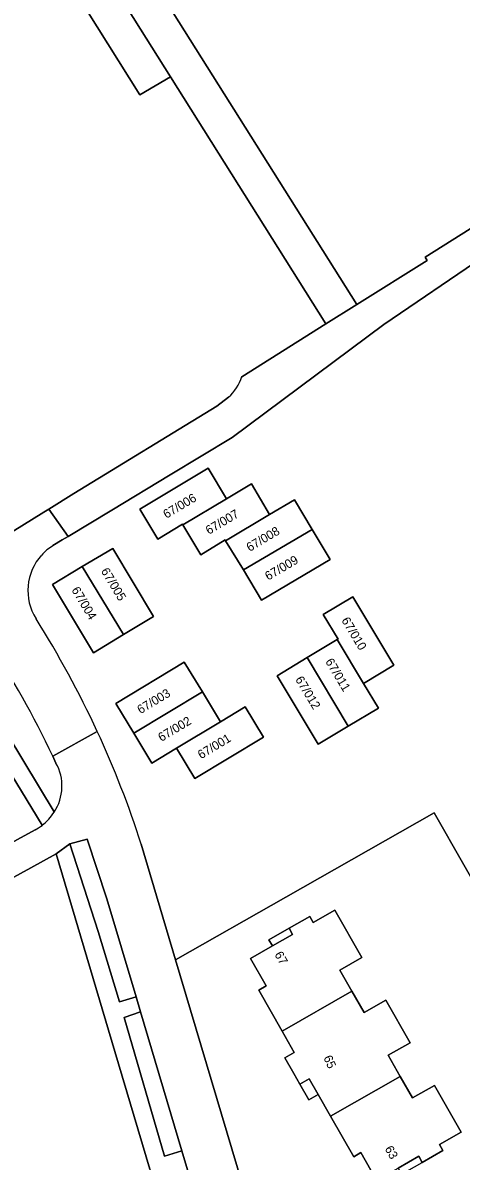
# Model space of a CAD drawing. Extents: x 158132 to 159664, y 385256 to 387218.
# Drawn here: x 158779.7 to 158829.4, y 386620.5 to 386749.8 of the extents above; entities that cross this region are included whole.
import ezdxf

# ---------------------------------------------------------------- set-up
doc = ezdxf.new("R2010")
doc.units = 0
for name, color, linetype in [('IMGEO_Berm_groen', 7, 'Continuous'), ('IMGEO_Erf', 7, 'Continuous'), ('IMGEO_Gemengd_bos', 7, 'Continuous'), ('IMGEO_Groenvoorziening', 7, 'Continuous'), ('IMGEO_Loofbos', 7, 'Continuous'), ('IMGEO_Pand', 7, 'Continuous'), ('IMGEO_Pand_nummerreeks', 7, 'Continuous'), ('IMGEO_Pand_overbouw', 7, 'Continuous'), ('IMGEO_Parkeervlak_open', 7, 'Continuous'), ('IMGEO_Rijbaan_lokaal_gesloten', 7, 'Continuous'), ('IMGEO_Voetpad_gesloten', 7, 'Continuous'), ('IMGEO_Voetpad_open', 7, 'Continuous')]:
    doc.layers.add(name, color=color, linetype=linetype)

msp = doc.modelspace()

# ---------------------------------------------------------------- linework, layer by layer
at = {"layer": 'IMGEO_Berm_groen'}
for points in [[(158775.73, 386679.59), (158772.63, 386677.75), (158783.24, 386660.19)], [(158783.43, 386665.75), (158783.08, 386666.53)]]:
    msp.add_lwpolyline(points, dxfattribs=at)
for centre, radius, start, end in [((158686.76, 386620.94), 106.56, 25.3313, 33.3917), ((158778.78, 386663.13), 5.34, 326.5723, 29.3728)]:
    msp.add_arc(centre, radius, start, end, dxfattribs=at)
at = {"layer": 'IMGEO_Erf'}
for points in [[(158839.81, 386636.46), (158826.35, 386660.11), (158809.51, 386650.52), (158797.01, 386643.41), (158808.08, 386606.17), (158832.23, 386594.34)], [(158819.82, 386618.36), (158818.03, 386621.5), (158817.22, 386621.04), (158814.6, 386625.63), (158813.19, 386628.12), (158812.12, 386627.51), (158811.11, 386629.29), (158810.43, 386630.5), (158809.42, 386632.26), (158810.48, 386632.86), (158809.09, 386635.3), (158806.44, 386639.95), (158807.3, 386640.44), (158805.52, 386643.57), (158808.01, 386644.99), (158807.61, 386645.69), (158809.89, 386646.98), (158812.24, 386648.33), (158812.63, 386647.65), (158815.07, 386649.04), (158818.14, 386643.66), (158815.65, 386642.24), (158817.03, 386639.83), (158818.4, 386637.41), (158820.87, 386638.82), (158823.62, 386633.99), (158821.13, 386632.57), (158822.51, 386630.14), (158823.89, 386627.71), (158826.39, 386629.13), (158829.42, 386623.81), (158826.96, 386622.41), (158827.35, 386621.74), (158824.99, 386620.4)]]:
    msp.add_lwpolyline(points, dxfattribs=at)
at = {"layer": 'IMGEO_Gemengd_bos'}
for points in [[(158804.53, 386709.63), (158814.08, 386715.63), (158796.45, 386743.69), (158792.95, 386741.63), (158783.28, 386757.12), (158786.68, 386759.23), (158770.04, 386785.73)], [(158831.89, 386723.22), (158820.63, 386715.54), (158803.45, 386702.74), (158796.4, 386698.49), (158789.76, 386694.48), (158784.81, 386691.49), (158784.15, 386691.09), (158783.09, 386690.44)], [(158778.46, 386692), (158782.07, 386694.24), (158782.63, 386694.59), (158785.45, 386696.37), (158801.69, 386706.29), (158803.02, 386707.3)], [(158793.12, 386656.52), (158797.01, 386643.41), (158809.51, 386650.52), (158826.35, 386660.11), (158839.81, 386636.46)]]:
    msp.add_lwpolyline(points, dxfattribs=at)
for points in [[(158812.52, 386692.26), (158814.55, 386688.86), (158806.76, 386684.26), (158804.7, 386687.68), (158802.69, 386691), (158802.63, 386691.1), (158799.86, 386689.41), (158797.84, 386692.81), (158797.8, 386692.87), (158794.99, 386691.18), (158792.95, 386694.59), (158800.72, 386699.23), (158802.79, 386695.77), (158805.61, 386697.45), (158807.68, 386693.98), (158810.49, 386695.66)], [(158794.52, 386682.4), (158791.1, 386680.33), (158787.69, 386678.27), (158783.03, 386686.04), (158786.42, 386688.07), (158789.88, 386690.13)], [(158821.79, 386676.87), (158818.34, 386674.8), (158820.02, 386672), (158816.61, 386669.95), (158813.21, 386667.91), (158808.54, 386675.67), (158811.95, 386677.72), (158815.36, 386679.77), (158815.46, 386679.83), (158813.74, 386682.63), (158817.12, 386684.63)], [(158806.97, 386668.7), (158799.21, 386664), (158797.13, 386667.43), (158794.33, 386665.74), (158792.28, 386669.13), (158790.23, 386672.52), (158797.99, 386677.22), (158800.05, 386673.83), (158802.1, 386670.44), (158804.9, 386672.14)]]:
    msp.add_lwpolyline(points, close=True, dxfattribs=at)
for centre, radius, start, end in [((158799.34, 386711.34), 5.47, 312.3991, 341.8129), ((158786.24, 386685.35), 5.98, 121.7641, 137.7233), ((158786.25, 386685.34), 6, 137.7119, 212.1777), ((158684.96, 386621.62), 113.66, 24.8208, 32.1691), ((158685.63, 386622.02), 112.89, 17.7969, 24.7835)]:
    msp.add_arc(centre, radius, start, end, dxfattribs=at)
at = {"layer": 'IMGEO_Groenvoorziening'}
for points in [[(158781.86, 386658.68), (158728.44, 386746.57)], [(158750.96, 386641.69), (158781.06, 386658.16)], [(158794.1, 386619.62), (158790.13, 386633), (158783.46, 386655.44), (158780.58, 386653.86), (158700.45, 386609.88), (158701.19, 386608.53), (158697.58, 386606.21)]]:
    msp.add_lwpolyline(points, dxfattribs=at)
for points in [[(158789.22, 386650.31), (158786.97, 386657.09), (158785.02, 386656.56), (158788.24, 386646.61), (158790.63, 386638.62), (158792.53, 386639.18)], [(158793.03, 386637.5), (158791.16, 386636.84), (158795.75, 386621.11), (158797.73, 386621.7)]]:
    msp.add_lwpolyline(points, close=True, dxfattribs=at)
msp.add_arc((158778.16, 386663.45), 6.04, 298.7274, 307.7499, dxfattribs=at)
at = {"layer": 'IMGEO_Loofbos'}
msp.add_lwpolyline([(158858.01, 386761.37), (158857.29, 386760.92), (158849.54, 386773.22), (158844.27, 386781.59), (158868.97, 386797.12), (158879.37, 386780.65), (158882, 386776.49), (158877.66, 386773.76), (158878.28, 386772.78), (158876.69, 386755.48), (158881.12, 386758.25), (158898.45, 386769.08), (158861.47, 386827.47), (158779.74, 386777.99), (158817.59, 386717.84), (158825.55, 386722.84), (158825.32, 386723.2), (158854.25, 386741.43), (158866.2, 386748.91)], close=True, dxfattribs=at)
at = {"layer": 'IMGEO_Pand'}
for points in [[(158802.79, 386695.77), (158800.72, 386699.23), (158792.95, 386694.59), (158794.99, 386691.18), (158797.8, 386692.87), (158797.84, 386692.81)], [(158807.68, 386693.98), (158805.61, 386697.45), (158802.79, 386695.77), (158797.84, 386692.81), (158799.86, 386689.41), (158802.63, 386691.1), (158802.69, 386691)], [(158812.52, 386692.26), (158810.49, 386695.66), (158807.68, 386693.98), (158802.69, 386691), (158804.7, 386687.68)], [(158814.55, 386688.86), (158812.52, 386692.26), (158804.7, 386687.68), (158806.76, 386684.26)], [(158786.42, 386688.07), (158791.1, 386680.33), (158794.52, 386682.4), (158789.88, 386690.13)], [(158786.42, 386688.07), (158783.03, 386686.04), (158787.69, 386678.27), (158791.1, 386680.33)], [(158813.74, 386682.63), (158815.46, 386679.83), (158815.36, 386679.77), (158818.34, 386674.8), (158821.79, 386676.87), (158817.12, 386684.63)], [(158815.36, 386679.77), (158811.95, 386677.72), (158816.61, 386669.95), (158820.02, 386672), (158818.34, 386674.8)], [(158800.05, 386673.83), (158797.99, 386677.22), (158790.23, 386672.52), (158792.28, 386669.13)], [(158811.95, 386677.72), (158808.54, 386675.67), (158813.21, 386667.91), (158816.61, 386669.95)], [(158802.1, 386670.44), (158800.05, 386673.83), (158792.28, 386669.13), (158794.33, 386665.74), (158797.13, 386667.43)], [(158806.97, 386668.7), (158804.9, 386672.14), (158802.1, 386670.44), (158797.13, 386667.43), (158799.21, 386664)], [(158817.03, 386639.83), (158815.65, 386642.24), (158818.14, 386643.66), (158815.07, 386649.04), (158812.63, 386647.65), (158812.24, 386648.33), (158809.89, 386646.98), (158810.28, 386646.29), (158808.01, 386644.99), (158805.52, 386643.57), (158807.3, 386640.44), (158806.44, 386639.95), (158809.09, 386635.3)], [(158823.62, 386633.99), (158820.87, 386638.82), (158818.4, 386637.41), (158817.03, 386639.83), (158809.09, 386635.3), (158810.48, 386632.86), (158809.42, 386632.26), (158810.43, 386630.5), (158811.11, 386629.29), (158812.18, 386629.89), (158813.19, 386628.12), (158814.6, 386625.63), (158822.51, 386630.14), (158821.13, 386632.57)], [(158814.6, 386625.63), (158817.22, 386621.04), (158818.03, 386621.5), (158819.82, 386618.36), (158822.26, 386619.75), (158824.6, 386621.09), (158824.99, 386620.4), (158827.35, 386621.74), (158826.96, 386622.41), (158829.42, 386623.81), (158826.39, 386629.13), (158823.89, 386627.71), (158822.51, 386630.14)]]:
    msp.add_lwpolyline(points, close=True, dxfattribs=at)
at = {"layer": 'IMGEO_Pand_overbouw'}
msp.add_lwpolyline([(158813.19, 386628.12), (158812.18, 386629.89), (158811.11, 386629.29), (158812.12, 386627.51)], close=True, dxfattribs=at)
at = {"layer": 'IMGEO_Parkeervlak_open'}
msp.add_lwpolyline([(158697.59, 386856.85), (158725.62, 386850), (158727.03, 386849.3), (158727.73, 386848.7), (158728.18, 386848.28), (158729.76, 386846.02), (158730.08, 386845.51), (158732.86, 386841.04), (158733.85, 386839.44), (158738.91, 386831.3), (158764.91, 386790.32), (158766.78, 386787.69), (158768.37, 386786.88), (158770.04, 386785.73), (158786.68, 386759.23), (158796.45, 386743.69), (158814.08, 386715.63), (158817.59, 386717.84), (158779.74, 386777.99), (158774.03, 386787.05), (158804.8, 386806.61)], dxfattribs=at)
at = {"layer": 'IMGEO_Rijbaan_lokaal_gesloten'}
for points in [[(158783.09, 386690.44), (158784.15, 386691.09), (158784.81, 386691.49), (158782.63, 386694.59), (158782.07, 386694.24), (158778.46, 386692)], [(158788.12, 386669.34), (158783.08, 386666.53), (158783.43, 386665.75)], [(158783.08, 386666.53), (158788.12, 386669.34)], [(158781.06, 386658.16), (158750.96, 386641.69), (158750.87, 386641.61), (158743.02, 386637.3), (158742.85, 386637.2), (158742.68, 386637.11), (158738.63, 386634.99), (158732.15, 386631.6), (158728.62, 386629.76), (158720.52, 386625.21), (158691.56, 386608.98)], [(158698.89, 386609.02), (158700.45, 386609.88), (158780.58, 386653.86), (158783.46, 386655.44), (158785.02, 386656.56), (158786.97, 386657.09), (158789.22, 386650.31), (158792.53, 386639.18), (158793.03, 386637.5), (158797.73, 386621.7), (158798.47, 386619.19), (158802.9, 386604.3), (158803.45, 386602.42), (158806.62, 386591.76), (158808.97, 386584.02), (158809.09, 386583.79), (158812.13, 386571.24), (158812.86, 386568.96), (158814.56, 386563.68), (158815.14, 386561.83), (158816.1, 386558.8), (158816.6, 386557.24), (158820.95, 386543.47), (158822.48, 386539.21)], [(158817.6, 386576.53), (158814.16, 386585.8), (158814.12, 386586), (158811.89, 386593.35), (158808.08, 386606.17), (158797.01, 386643.41), (158793.12, 386656.52)]]:
    msp.add_lwpolyline(points, dxfattribs=at)
for centre, radius, start, end in [((158786.24, 386685.35), 5.98, 121.7641, 137.7233), ((158786.25, 386685.34), 6, 137.7119, 212.1777), ((158684.96, 386621.62), 113.66, 24.8208, 32.1691), ((158686.76, 386620.94), 106.56, 25.3313, 33.3917), ((158685.63, 386622.02), 112.89, 17.7969, 24.7835), ((158778.78, 386663.13), 5.34, 326.5723, 29.3728), ((158778.23, 386663.38), 5.94, 307.638, 327.506), ((158778.16, 386663.45), 6.04, 298.7274, 307.7499)]:
    msp.add_arc(centre, radius, start, end, dxfattribs=at)
at = {"layer": 'IMGEO_Voetpad_gesloten'}
for points in [[(158854.25, 386741.43), (158825.32, 386723.2), (158825.55, 386722.84), (158817.59, 386717.84), (158814.08, 386715.63), (158804.53, 386709.63)], [(158820.63, 386715.54), (158831.89, 386723.22)], [(158803.02, 386707.3), (158801.69, 386706.29), (158785.45, 386696.37), (158782.63, 386694.59), (158784.81, 386691.49), (158789.76, 386694.48), (158796.4, 386698.49), (158803.45, 386702.74), (158820.63, 386715.54)]]:
    msp.add_lwpolyline(points, dxfattribs=at)
msp.add_arc((158799.34, 386711.34), 5.47, 312.3991, 341.8129, dxfattribs=at)
at = {"layer": 'IMGEO_Voetpad_open'}
for points in [[(158750.1, 386714.47), (158739.4, 386732.23), (158733.36, 386742.16), (158727.95, 386751.06), (158725.88, 386754.49), (158722, 386760.84), (158721.96, 386760.87), (158721.95, 386760.88), (158721.92, 386760.9), (158721.88, 386760.92), (158720.25, 386759.85), (158722.15, 386756.72), (158722.23, 386756.59), (158722.88, 386755.56), (158723.22, 386755), (158727.55, 386748.04), (158728.44, 386746.57), (158781.86, 386658.68)], [(158783.24, 386660.19), (158772.63, 386677.75), (158775.73, 386679.59), (158774.75, 386681.17), (158771.57, 386679.21), (158764.49, 386690.77), (158750.1, 386714.47)], [(158793.03, 386637.5), (158792.53, 386639.18), (158790.63, 386638.62), (158788.24, 386646.61), (158785.02, 386656.56), (158783.46, 386655.44), (158790.13, 386633), (158794.1, 386619.62), (158794.82, 386617.19), (158806.58, 386577.59), (158806.66, 386577.35)], [(158808.29, 386579.04), (158801.51, 386601.88), (158803.45, 386602.42), (158802.9, 386604.3), (158800.95, 386603.8), (158796.54, 386618.61), (158798.47, 386619.19), (158797.73, 386621.7), (158795.75, 386621.11), (158791.16, 386636.84), (158793.03, 386637.5)]]:
    msp.add_lwpolyline(points, dxfattribs=at)
for points in [[(158786.68, 386759.23), (158783.28, 386757.12), (158792.95, 386741.63), (158796.45, 386743.69)], [(158809.89, 386646.98), (158807.61, 386645.69), (158808.01, 386644.99), (158810.28, 386646.29)], [(158812.18, 386629.89), (158811.11, 386629.29), (158812.12, 386627.51), (158813.19, 386628.12)], [(158824.6, 386621.09), (158822.26, 386619.75), (158822.65, 386619.06), (158824.99, 386620.4)]]:
    msp.add_lwpolyline(points, close=True, dxfattribs=at)
msp.add_arc((158778.23, 386663.38), 5.94, 307.638, 327.506, dxfattribs=at)

# ---------------------------------------------------------------- texts
at = {"layer": 'IMGEO_Pand_nummerreeks'}
for s, rotation, p in [('67/006', 30.8538, (158795.97, 386693.48)), ('67/007', 30.8652, (158800.79, 386691.66)), ('67/008', 30.8538, (158805.42, 386689.72)), ('67/009', 30.5845, (158807.52, 386686.45)), ('67/005', 300.951, (158788.5, 386687.56)), ('67/004', 300.9395, (158785.16, 386685.41)), ('67/010', 300.9739, (158815.79, 386681.96)), ('67/011', 300.9853, (158813.96, 386677.28)), ('67/012', 300.9739, (158810.55, 386675.25)), ('67/003', 31.2033, (158793.03, 386671.29)), ('67/002', 31.2033, (158795.4, 386668.14)), ('67/001', 31.1976, (158799.9, 386666.17)), ('67', 299.9688, (158808.2, 386644.01)), ('65', 293.7947, (158813.77, 386632.3)), ('63', 299.7322, (158820.71, 386621.94))]:
    msp.add_text(s, height=1, rotation=rotation, dxfattribs=at).set_placement(p)

doc.saveas('drawing.dxf')
